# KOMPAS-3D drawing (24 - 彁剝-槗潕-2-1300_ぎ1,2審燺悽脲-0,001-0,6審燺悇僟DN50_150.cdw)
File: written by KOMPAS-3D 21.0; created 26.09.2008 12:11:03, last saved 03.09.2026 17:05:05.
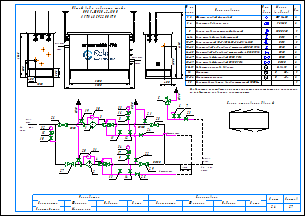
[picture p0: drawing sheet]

Sheets 1-2: A3, landscape

Document properties: Наименование: Макро:21; Автор: RaskoAdmin; Форматы листов документа: 2xA3; Полное имя файла: \\UR38nt01\Departments\КТО\КБ ПУРДГ\Заявки\Прайс-лист на типовые шкафы ГРПШ\ПРДГ_стандарт_20_03_2026\ПРДГ с РДГ(Н, В)\ПРДГ-ШУЭО-2-1300_до1,2МПа_Рвых-0,001-0,6МПа_РДГ_DN50_150.cdw

Title block, sheet 1: Наименование: Пункт учета газа / ПУГ-Ш-400-Р / ЛГТИ.485922.001ТУ; designation: ЛГТИ.03.4411141; sheet number: 1; Количество листов документа: 2; organisation: ООО "ЭЛЬСТЕР Газэлектроника"; Форматы листов документа: A3; stored path: C:\Рабочие документы\Компас\ПУГ\Схема.cdw; Разработал: Устинов; Проверил: Кошкин; Утвердил: Кошкин
Title block, sheet 2: sheet number: 2; stored path: D:\Рабочие документы\Заявки\ПУРДГ\ПУРДГ-ШУЭО-2-100-Р 4411220.cdw; designation, second copy: ЛГТИ.03.4411141-

Views: Вид 1, Вид 2
Referenced files: wcvoit.frw
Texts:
  Normal
  № на
  схеме
  Усл.
  обозн.
  Марка
  (модель)
  Кол.
  Фильтр газовый фланцевый
  ФГ 16-50
  Регулятор давления газа
  РДГ-50
  Клапан предохранительный сбросной
  КПС DN20
  Кран шаровой газовый латунный
  DN15
  Кран кнопочный VE-РАСКО-НЗ-1,6-G1/2-М20
  Кран шаровой "под приварку" штуцерный DN20 PN16
  Кран шаровой "под приварку" штуцерный п/п DN20 PN16
  DN20
  Кран шаровой фланцевый DN50 PN16
  Кран шаровой фланцевый DN150 PN16
  DN50
  DN150
  Индикатор перепада давления
  Delta 15
  Манометр
  Манометр-напоромер
  Электрообогреватель взрывозащищенный 1000Вт
  0...     МПа
  0...     кПа
  Общий вид и габариты шкафа
  ПРДГ-ШУЭО-2-1300
  Выход газа
  Вход газа
  logo-rasko-ge.png
  Вход
  газа
  PDI
  Выход
  Р=     кПа
  Импульс DN20
  ≥5DN
  HYSWLongFangSong
  Р=       МПа
  Схема открывания дверей
  Предприятие изготовитель может заменять комплектующие на аналогичные,
  не ухудшающие заявленных характеристик.
  Должность
  Конструктор
  Фамилия
  Подпись
  Дата
  Согласовано
  Максимкин
  Лист
  Листов
  POLYLINE_STYLE_0.18_RGB_0_0_0
  POLYLINE_STYLE_0.50_RGB_0_0_0
  POLYLINE_STYLE_0.34_RGB_0_0_0
  PHANTOM_RGB_0_0_0_SC_1_THICK_0.18
  K5LT_THIN_RGB_0_0_0_THICK_0.18
  K5LT32769_RGB_0_0_0_THICK_0.18
  K5LT12_RGB_0_0_0_SC_1_THICK_0.18
  K5LT_DASHED_RGB_0_0_0_SC_1_THICK_0.18
  ACISOTGL_RGB_0_0_0_SC_0.8_THICK_0.25
  CONTINUOUS_RGB_0_127_31_THICK_0.3
  CONTINUOUS_RGB_0_0_255_THICK_0.35
  CONTINUOUS_RGB_255_0_0_THICK_0.35
  POLYLINE_STYLE_0.25_RGB_0_0_0
  CONTINUOUS_RGB_0_0_0_THICK_0.5
  POLYLINE_STYLE_0.35_RGB_0_0_255
  CONTINUOUS_RGB_0_0_0_THICK_0.4
  CONTINUOUS_RGB_0_0_0_THICK_0.35
  Без оформления
Dimensions and other numbers on the sheet: 1; 1, 2; 2; 3, 4; 5; 6-14; 9; 15-17; 3; 18-23; 24-25; 6; 26-27; 28-29; 30-31; 32; 33-34; 35; 400; 1050; 500; 305; 1565; 3300; 1000; 4130; 3000; 4; 10; 27; 28; 29; 23; 8; 12; 19; 20; 21; 22; 25; 24; 30; 31; 15; 16; 26; 7; 11; 14; 13; 33; 17; 34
